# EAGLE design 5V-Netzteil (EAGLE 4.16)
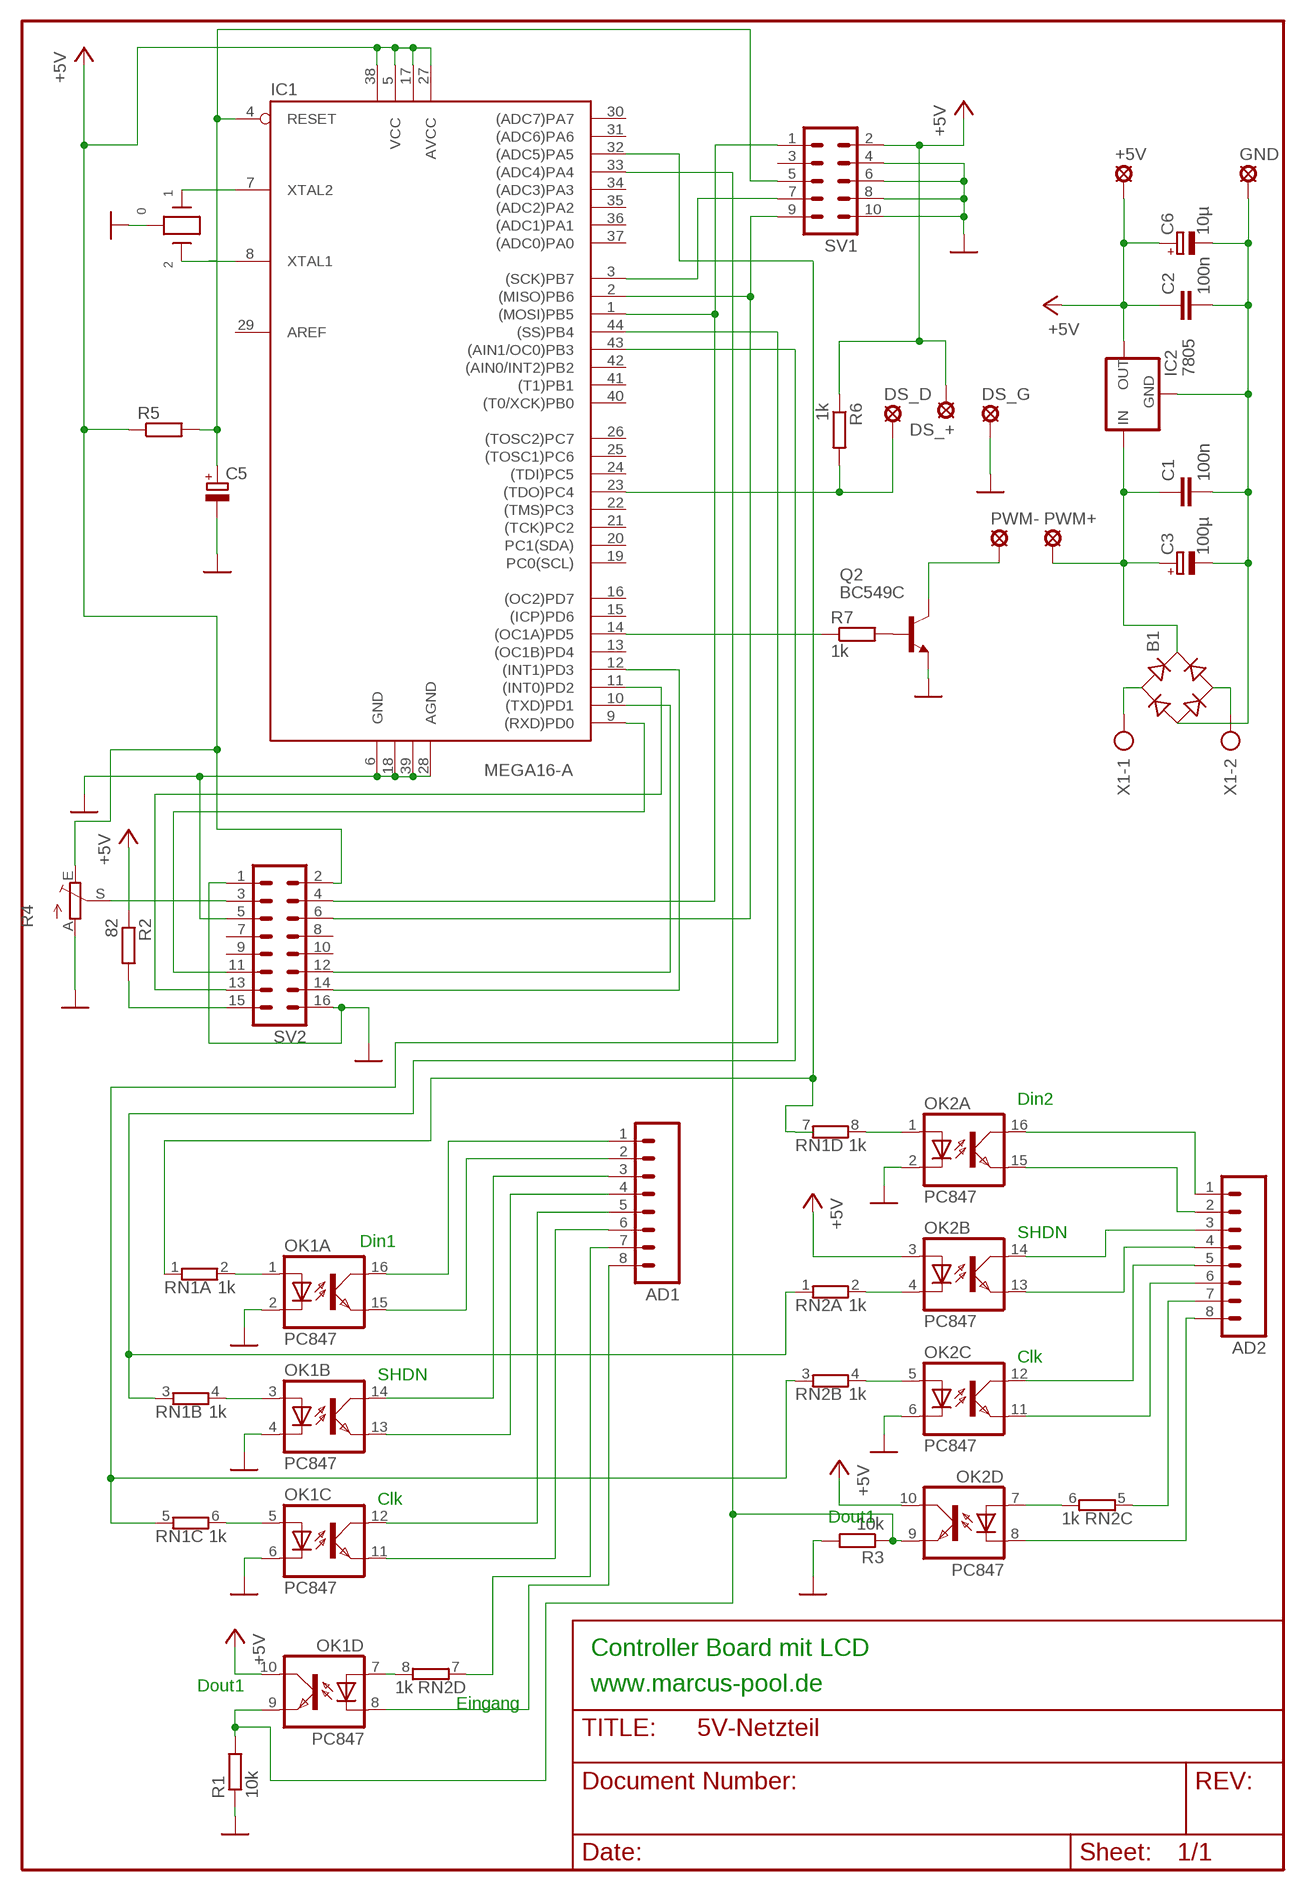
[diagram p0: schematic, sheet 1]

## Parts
+5V  DS1820  LSP10  [LSP10]
AD1  M08  [08P]
AD2  M08  [08P]
B1  B-DIL  [B-DIL]
C1  100n  C-EU050-030X075  [C050-030X075]
C2  100n  C-EU050-030X075  [C050-030X075]
C3  100µ  CPOL-EUE5-13  [E5-13]
C5  CPOL-EUE2-5  [E2-5]
C6  10µ  CPOL-EUE2,5-6E  [E2,5-6E]
DS_+  DS1820  LSP10  [LSP10]
DS_D  DS1820  LSP10  [LSP10]
DS_G  DS1820  LSP10  [LSP10]
GND  DS1820  LSP10  [LSP10]
IC1  MEGA16-A  [TQFP44]
IC2  7805  78XXS  [78XXS]
OK1  PC847  [DIL16]
OK2  PC847  [DIL16]
PWM+  DS1820  LSP10  [LSP10]
PWM-  DS1820  LSP10  [LSP10]
Q2  BC549C  [TO92-EBC]
Q/1  SCHWINGER/3"  [SCHWINGER/3]
R1  10k  R-EU_0207/10  [0207/10]
R2  82  R-EU_0207/10  [0207/10]
R3  10k  R-EU_0207/10  [0207/10]
R4  TRIM_EU-LI10  [LI10]
R5  R-EU_0207/10  [0207/10]
R6  1k  R-EU_0207/10  [0207/10]
R7  1k  R-EU_0207/10  [0207/10]
RN1  1k  E4R  [SIL8]
RN2  1k  E4R  [SIL8]
SV1  ML10  [ML10]
SV2  ML16  [ML16]
X1  AK500/2  [AK500/2]

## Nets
+5V: +5V.MP C2.1 C6.+ DS_+.MP IC1.5(VCC) IC1.17(VCC1) IC1.27(AVCC) IC1.38(VCC2) IC2.OUT OK1.10(D:COL) OK2.3(B:A) OK2.10(D:COL) R2.1 R4.E R5.1 R6.1 SV1.2 SV2.2
CLK: IC1.44((SS)PB4) RN1.5 RN2.3
DIN: IC1.32((ADC5)PA5) RN1.1 RN1.7
DIN2A: OK1.1(A:A) RN1.2
DIN2B: OK2.1(A:A) RN1.8
DOUT: IC1.33((ADC4)PA4) OK1.9(D:EMIT) OK2.9(D:EMIT) R1.2 R3.1
GND: B1.- C1.2 C2.2 C3.- C5.- C6.- DS_G.MP GND.MP IC1.6(GND) IC1.18(GND1) IC1.28(AGND) IC1.39(GND2) IC2.GND OK1.2(A:C) OK1.4(B:C) OK1.6(C:C) OK2.2(A:C) OK2.6(C:C) Q2.E Q/1.0 R1.1 R3.2 R4.A SV1.4 SV1.6 SV1.8 SV1.10 SV2.1 SV2.5 SV2.16 ; supply symbol labelled 
N$1: Q2.B R7.2
N$2: OK2.4(B:C) RN2.2
N$3: B1.AC1 X1.1
N$4: B1.AC2 X1.2
N$5: B1.+ C1.1 C3.+ IC2.IN PWM+.MP
N$6: PWM-.MP Q2.C
N$7: IC1.12((INT1)PD3) SV2.14
N$8: IC1.7(XTAL2) Q/1.1
N$9: IC1.1((MOSI)PB5) SV1.1 SV2.4
N$10: IC1.8(XTAL1) Q/1.2
N$12: IC1.10((TXD)PD1) SV2.12
N$13: IC1.11((INT0)PD2) SV2.13
N$14: IC1.9((RXD)PD0) SV2.11
N$17: R4.S SV2.3
N$18: OK1.5(C:A) RN1.6
N$19: OK1.3(B:A) RN1.4
N$20: OK1.7(D:A) RN2.8
N$21: OK2.7(D:A) RN2.6
N$22: OK2.5(C:A) RN2.4
N$24: R2.2 SV2.15
N$26: IC1.2((MISO)PB6) SV1.9 SV2.6
N$27: IC1.3((SCK)PB7) SV1.7
N$28: AD2.6 OK2.11(C:EMIT)
N$30: AD1.2 OK1.15(A:EMIT)
N$34: AD1.1 OK1.16(A:COL)
N$36: AD2.1 OK2.16(A:COL)
N$37: AD2.2 OK2.15(A:EMIT)
N$38: AD2.3 OK2.14(B:COL)
N$39: AD2.4 OK2.13(B:EMIT)
N$40: AD1.3 OK1.14(B:COL)
N$41: AD1.4 OK1.13(B:EMIT)
N$42: AD1.5 OK1.12(C:COL)
N$43: AD1.6 OK1.11(C:EMIT)
N$44: AD1.7 RN2.7
N$45: AD1.8 OK1.8(D:C)
N$46: AD2.5 OK2.12(C:COL)
N$48: AD2.7 RN2.5
N$49: AD2.8 OK2.8(D:C)
N$52: IC1.14((OC1A)PD5) R7.1
N$53: DS_D.MP IC1.23((TDO)PC4) R6.2
RESET: C5.+ IC1.4(RESET) R5.2 SV1.5
SHDN: IC1.43((AIN1/OC0)PB3) RN1.3 RN2.1
Unconnected: IC1.13((OC1B)PD4) IC1.15((ICP)PD6) IC1.16((OC2)PD7) IC1.19(PC0(SCL)) IC1.20(PC1(SDA)) IC1.21((TCK)PC2) IC1.22((TMS)PC3) IC1.24((TDI)PC5) IC1.25((TOSC1)PC6) IC1.26((TOSC2)PC7) IC1.30((ADC7)PA7) IC1.31((ADC6)PA6) IC1.34((ADC3)PA3) IC1.35((ADC2)PA2) IC1.36((ADC1)PA1) IC1.37((ADC0)PA0) IC1.40((T0/XCK)PB0) IC1.41((T1)PB1) IC1.42((AIN0/INT2)PB2) SV1.3 SV2.7 SV2.8 SV2.9 SV2.10

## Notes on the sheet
- Din2
- SHDN
- Din1
- Clk
- SHDN
- Clk
- Dout1
- Controller Board mit LCD
- Dout1 | www.marcus-pool.de
- Eingang

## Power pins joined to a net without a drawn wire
AREF: IC1.29(AREF)

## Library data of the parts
+5V DS_+ DS_D DS_G GND PWM+ PWM- = solpad:LSP10: SOLDER PAD
AD1 AD2 = con-amp-quick:M08: AMP QUICK CONNECTOR
B1 = rectifier:B-DIL: RECTIFIER
C1 C2 = rcl:C-EU: CAPACITOR, European symbol
C3 C5 C6 = rcl:CPOL-EU: POLARIZED CAPACITOR, European symbol
IC1 = atmel:MEGA16: MICROCONTROLLER 16 Kbytes FLASH 1 kbytes SRAM 512 bytes EEPROM USART 8-channel 10 bit ADC
IC2 = v-reg:78XXS: VOLTAGE REGULATOR
OK1 OK2 = optocoupler:PC847: SHARP OPTO COUPLER
Q2 = transistor-npn:BC549*: NPN Transistor
Q/1 = crystal2:SCHWINGER/3: Schwinger 4 MHz
R1-R3 R5-R7 = rcl:R-EU_: RESISTOR, European symbol
R4 = pot:TRIM_EU-: POTENTIOMETER
RN1 RN2 = resistor-sil:E4R: SIL RESISTOR
SV1 = con-harting-ml:ML10: HARTING
SV2 = con-harting-ml:ML16: HARTING
X1 = con-ptr500:AK500/2: CONNECTOR

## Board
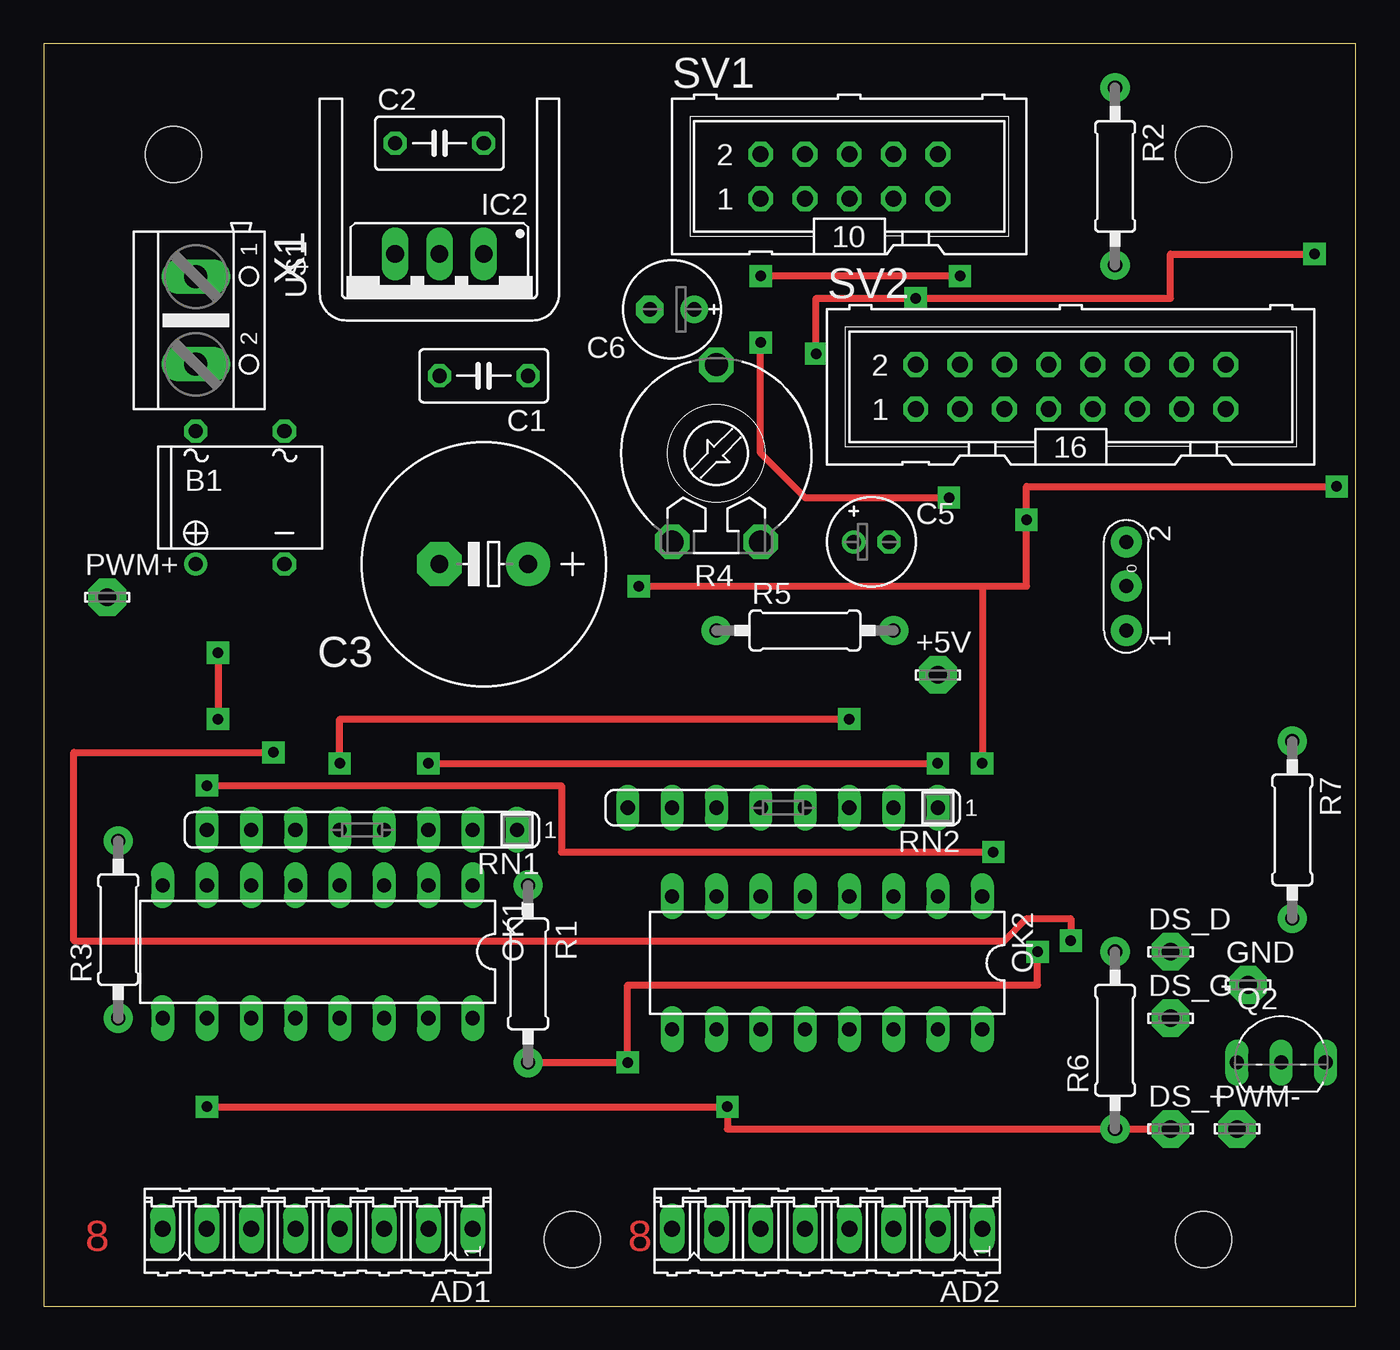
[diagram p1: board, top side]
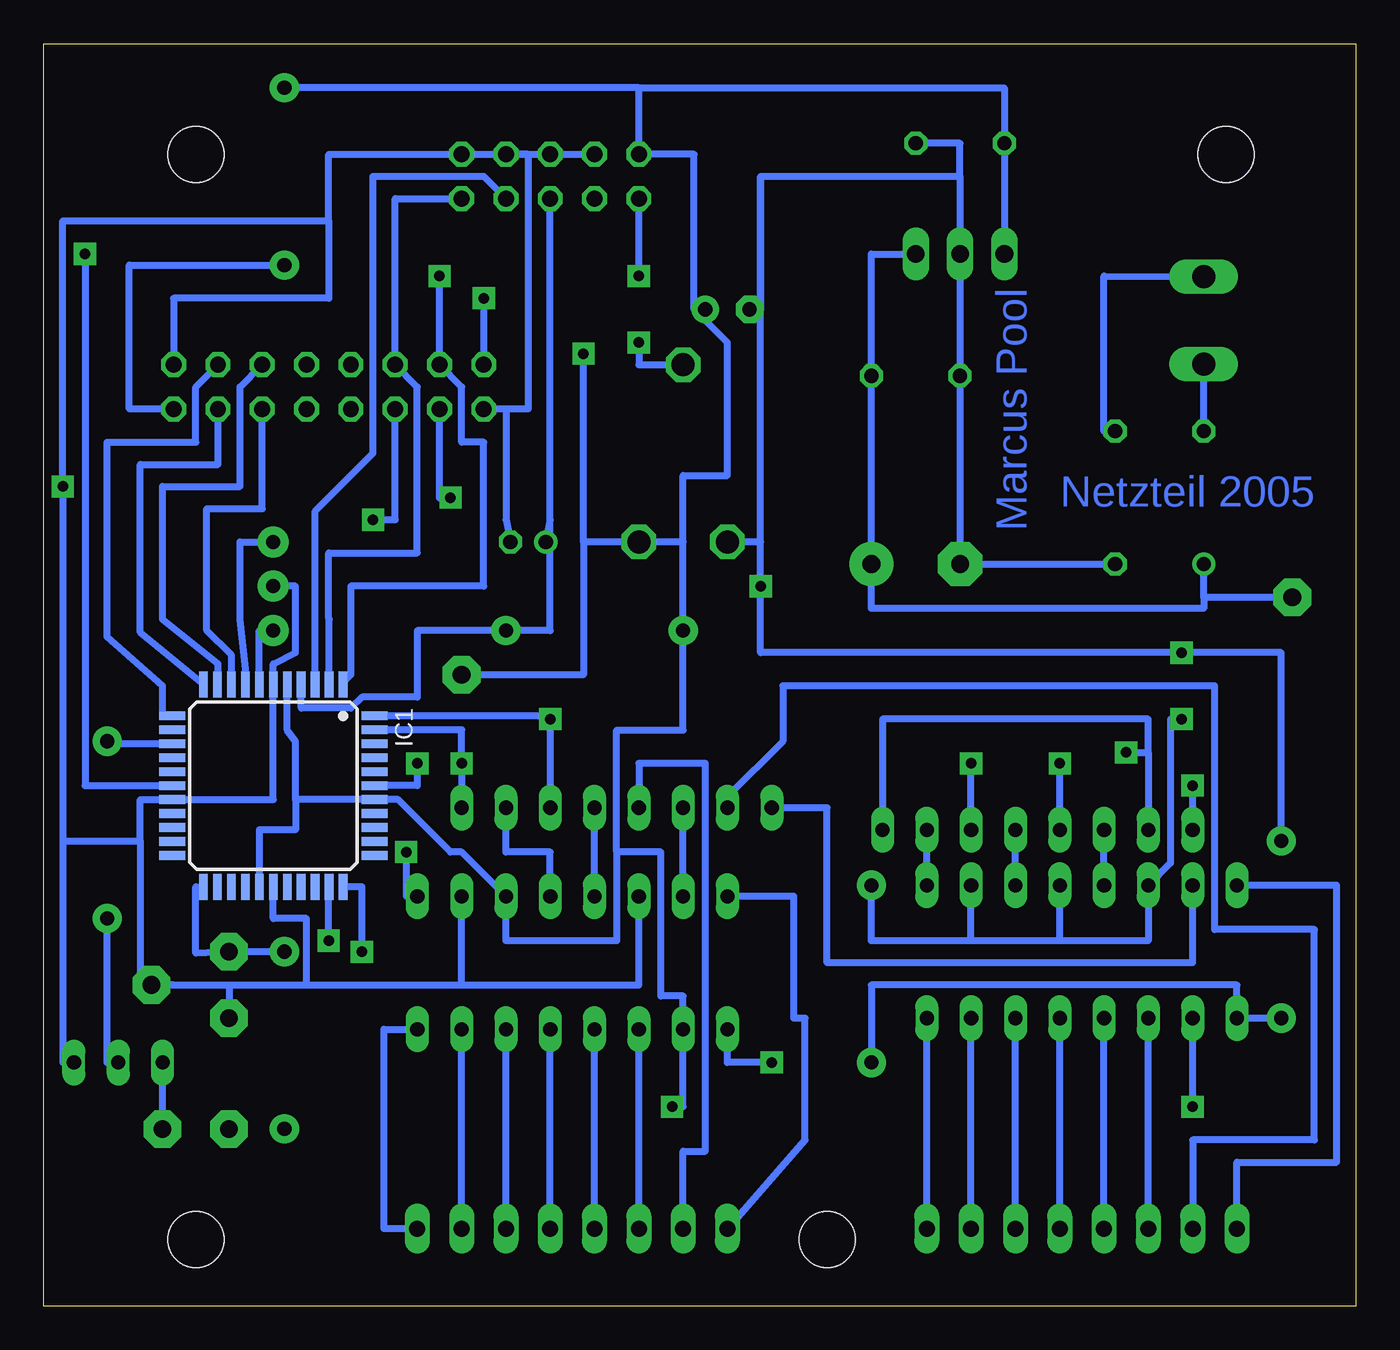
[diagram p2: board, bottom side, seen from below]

Size 75.23 x 72.38 mm. Coordinates in mm from the lower left corner, seen from the top.
Outline: 0,0 75.23,0 75.23,72.38 0,72.38 0,0
Copper layers (1*16): Top 0.035mm / dielectric 1.5mm / Bottom 0.035mm
Design rules "default": minimum track width 10mil, minimum drill 24mil, track to track 8mil, track to pad 8mil, pad to pad 8mil, via to via 8mil, smd to smd 8mil, copper to edge 40mil, drill to drill 8mil, minimum pad ring 10mil, minimum via ring 8mil, stop-mask expansion 4mil, vias tented up to drill 0mil, thermal gap 10mil
Holes 3.2 mm at 7.46,66.04 66.51,66.04 66.51,3.81 30.31,3.81

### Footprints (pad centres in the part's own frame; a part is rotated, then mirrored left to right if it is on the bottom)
LSP10 = drill 1.016 pad 2.159 octagon: MP 0,0
08P = drill 0.914 long: 1 -8.89,0; 2 -6.35,0; 3 -3.81,0; 4 -1.27,0; 5 1.27,0; 6 3.81,0; 7 6.35,0; 8 8.89,0
B-DIL = drill 0.813 round: + -2.54,-3.81 | drill 0.813 octagon: - 2.54,-3.81; AC1 2.54,3.81; AC2 -2.54,3.81
C050-030X075 = drill 0.813 octagon: 1 -2.54,0; 2 2.54,0
E5-13 = drill 1.016 pad 2.54 round: + -2.54,0 | drill 1.016 pad 2.54 octagon: - 2.54,0
E2-5 = drill 0.813 pad 1.27 round: + -1.016,0 | drill 0.813 pad 1.27 octagon: - 1.016,0
E2,5-6E = drill 0.813 pad 1.575 round: + -1.27,0 | drill 0.813 pad 1.575 octagon: - 1.27,0
TQFP44 = smd 1.5 x 0.5: 1 -5.8,4; 2 -5.8,3.2; 3 -5.8,2.4; 4 -5.8,1.6; 5 -5.8,0.8; 6 -5.8,0; 7 -5.8,-0.8; 8 -5.8,-1.6; 9 -5.8,-2.4; 10 -5.8,-3.2; 11 -5.8,-4; 23 5.8,-4; 24 5.8,-3.2; 25 5.8,-2.4; 26 5.8,-1.6; 27 5.8,-0.8; 28 5.8,0; 29 5.8,0.8; 30 5.8,1.6; 31 5.8,2.4; 32 5.8,3.2; 33 5.8,4 | smd 0.5 x 1.5: 12 -4,-5.8; 13 -3.2,-5.8; 14 -2.4,-5.8; 15 -1.6,-5.8; 16 -0.8,-5.8; 17 0,-5.8; 18 0.8,-5.8; 19 1.6,-5.8; 20 2.4,-5.8; 21 3.2,-5.8; 22 4,-5.8; 34 4,5.8; 35 3.2,5.8; 36 2.4,5.8; 37 1.6,5.8; 38 0.8,5.8; 39 0,5.8; 40 -0.8,5.8; 41 -1.6,5.8; 42 -2.4,5.8; 43 -3.2,5.8; 44 -4,5.8
78XXS = drill 1.016 long: GND 0,-2.54; IN -2.54,-2.54; OUT 2.54,-2.54
DIL16 = drill 0.813 long: 1 -8.89,-3.81; 2 -6.35,-3.81; 3 -3.81,-3.81; 4 -1.27,-3.81; 5 1.27,-3.81; 6 3.81,-3.81; 7 6.35,-3.81; 8 8.89,-3.81; 9 8.89,3.81; 10 6.35,3.81; 11 3.81,3.81; 12 1.27,3.81; 13 -1.27,3.81; 14 -3.81,3.81; 15 -6.35,3.81; 16 -8.89,3.81
TO92-EBC = drill 0.813 long: B 0,-1.27; C -2.54,-1.27; E 2.54,-1.27
SCHWINGER/3 = drill 0.8 pad 1.778 round: 0 0,0; 1 -2.54,0; 2 2.54,0
0207/10 = drill 0.813 pad 1.676 round: 1 -5.08,0; 2 5.08,0
LI10 = drill 1.321 octagon: A -2.54,-5.08; E 2.54,-5.08; S 0,5.08
SIL8 = drill 0.813 long: 1 -8.89,0; 2 -6.35,0; 3 -3.81,0; 4 -1.27,0; 5 1.27,0; 6 3.81,0; 7 6.35,0; 8 8.89,0
ML10 = drill 0.914 octagon: 1 -5.08,-1.27; 2 -5.08,1.27; 3 -2.54,-1.27; 4 -2.54,1.27; 5 0,-1.27; 6 0,1.27; 7 2.54,-1.27; 8 2.54,1.27; 9 5.08,-1.27; 10 5.08,1.27
ML16 = drill 0.914 octagon: 1 -8.89,-1.27; 2 -8.89,1.27; 3 -6.35,-1.27; 4 -6.35,1.27; 5 -3.81,-1.27; 6 -3.81,1.27; 7 -1.27,-1.27; 8 -1.27,1.27; 9 1.27,-1.27; 10 1.27,1.27; 11 3.81,-1.27; 12 3.81,1.27; 13 6.35,-1.27; 14 6.35,1.27; 15 8.89,-1.27; 16 8.89,1.27
AK500/2 = drill 1.321 long: 1 -2.515,0; 2 2.515,0

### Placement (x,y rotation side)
+5V  51.27,36.19 0 top
AD1  15.71,4.44 180 top
AD2  44.92,4.44 180 top
B1  11.27,46.35 0 top
C1  25.23,53.34 180 top
C2  22.7,66.67 0 top
C3  25.23,42.54 180 top
C5  47.46,43.81 0 top
C6  36.03,57.14 180 top
DS_+  64.61,10.15 0 top
DS_D  64.61,20.32 0 top
DS_G  64.61,16.51 0 top
GND  69.05,18.41 0 top
IC1  62.06,29.84 270 bottom
IC2  22.7,57.78 180 top
OK1  15.71,20.32 180 top
OK2  44.92,19.68 180 top
PWM+  3.64,40.63 0 top
PWM-  68.41,10.15 0 top
Q2  70.95,15.23 0 top
Q/1  62.06,41.27 90 top
R1  27.77,19.05 270 top
R2  61.43,64.77 270 top
R3  4.28,21.59 90 top
R4  38.57,48.89 0 top
R5  43.65,38.73 0 top
R6  61.43,15.23 90 top
R7  71.59,27.3 270 top
RN1  18.25,27.3 180 top
RN2  42.38,28.57 180 top
SV1  46.19,64.77 0 top
SV2  58.89,52.7 0 top
U$1  [D01S]  22.7,57.78 0 top
X1  8.73,56.51 270 top

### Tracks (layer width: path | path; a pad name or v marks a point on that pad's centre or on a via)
+5V  (via drill 0.6 pad 1.27)
  Top 0.406: v9.36,11.42 v39.2,11.42 39.2,10.15 R6.1 DS_+.MP | v44.28,54.6 44.28,57.78 v50,57.78 64.61,57.78 64.61,60.32 v72.86,60.32
  Bottom 0.406: IC2.OUT C2.1 20.15,69.84 41.11,69.84 | 41.11,69.84 R2.1 | 42.38,26.03 39.84,26.03 39.84,17.78 38.57,17.78 OK2.10 38.57,11.42 v39.2,11.42 | 42.38,26.03 42.38,33.02 38.57,33.02 R5.1 38.57,43.81 | 38.57,43.81 38.57,47.62 36.03,47.62 36.03,55.24 37.3,56.51 C6.+ 37.94,57.14 37.94,66.04 SV1.2 41.11,69.84 | v9.36,11.42 OK1.10 | 42.38,26.03 42.38,20.95 48.73,20.95 OK2.3 51.27,26.03 51.91,26.03 54.91,29.04 IC1.38 60.8,29.04 60.8,29.21 | 44.28,43.81 44.28,36.19 +5V.MP | 44.28,43.81 v44.28,54.6 | v50,57.78 SV2.2 | 60.8,29.21 60.8,32.38 61.27,33.02 IC1.5 | 38.57,43.81 R4.E 44.28,43.81 | IC1.27 62.87,27.3 60.8,27.3 60.8,29.21 | IC1.17 72.86,29.84 v72.86,60.32
CLK  (via drill 0.6 pad 1.27)
  Top 0.406: v16.98,31.11 16.98,33.65 v46.19,33.65
  Bottom 0.406: RN2.3 v46.19,33.65 46.19,33.84 IC1.44 | RN1.5 v16.98,31.11
DIN  (via drill 0.6 pad 1.27)
  Top 0.406: v58.89,20.95 58.89,22.22 56.35,22.22 55.08,20.95 1.74,20.95 1.74,31.75 v13.17,31.75
  Bottom 0.406: 11.9,31.75 RN1.7 | 11.9,31.75 11.9,33.65 27.14,33.65 RN1.1 | IC1.32 58.89,24.04 v58.89,20.95 | v13.17,31.75 11.9,31.75
DIN2A
  Bottom 0.406: OK1.1 RN1.2
DIN2B  (via drill 0.6 pad 1.27)
  Top 0.406: v54.45,26.03 29.68,26.03 29.68,29.84 v9.36,29.84
  Bottom 0.406: v54.45,26.03 54.45,23.49 OK2.1 | RN1.8 v9.36,29.84
DOUT  (via drill 0.6 pad 1.27)
  Top 0.406: R1.2 v33.49,13.96 33.49,18.41 56.98,18.41 v56.98,20.32
  Bottom 0.406: R3.1 OK1.9 6.82,18.41 27.77,18.41 R1.2 | v33.49,13.96 36.03,13.96 OK2.9 | IC1.33 56.98,24.04 v56.98,20.32
GND  (via drill 0.6 pad 1.27)
  Top 0.406: v10,37.46 v10,33.65 | v74.13,46.98 56.35,46.98 v56.35,45.08 56.35,41.27 53.81,41.27 | v34.12,41.27 53.81,41.27 | 53.81,41.27 v53.81,31.11
  Bottom 0.406: SV1.4 SV1.6 47.46,66.04 | 47.46,66.04 SV1.10 58.89,66.04 58.89,62.22 | 47.46,66.04 SV1.8 | 16.98,20.95 OK1.4 | 16.98,20.95 22.06,20.95 | 22.06,20.95 OK1.2 | 16.98,20.95 11.9,20.95 OK1.6 10.63,25.39 10.63,33.65 v10,33.65 | OK2.6 41.11,18.41 51.27,18.41 | 51.27,18.41 OK2.2 | 67.78,18.41 64.61,18.41 | 64.61,18.41 60.16,18.41 | 60.16,18.41 51.27,18.41 | 58.89,62.22 74.13,62.22 v74.13,46.98 74.13,26.67 | 58.89,62.22 58.89,57.78 67.78,57.78 SV2.16 | B1.- C3.- C1.2 IC2.GND 22.7,64.77 | C2.2 22.7,66.67 22.7,64.77 | 34.12,57.14 C6.- | 34.12,64.77 22.7,64.77 | 34.12,43.81 34.12,57.14 | 34.12,64.77 34.12,57.14 | 67.78,18.41 GND.MP | 67.78,18.41 69.69,18.41 69.69,26.67 | v34.12,41.27 34.12,37.46 v10,37.46 4.28,37.46 R3.2 | v34.12,41.27 34.12,43.81 | R1.1 27.77,20.95 22.06,20.95 | 34.12,43.81 R4.A | 47.46,66.04 47.46,51.43 48.73,51.43 | Q/1.0 60.8,41.27 60.8,37.46 62.06,36.82 IC1.6 62.06,29.04 IC1.18 69.69,29.04 69.69,26.67 | 48.73,51.43 SV2.1 | SV2.5 55.08,45.08 v56.35,45.08 | v34.12,41.27 34.12,64.77 | 74.13,26.67 74.13,13.96 Q2.E | 64.61,18.41 DS_G.MP | 74.13,26.67 69.69,26.67 | C5.- 48.73,45.08 48.73,51.43 | IC1.28 62.06,22.22 60.16,22.22 60.16,18.41 | IC1.39 53.81,29.84 v53.81,31.11
N$1
  Bottom 0.406: Q2.B 71.59,13.96 R7.2
N$2
  Bottom 0.406: OK2.4 46.19,26.03 48.73,26.03 RN2.2
N$3
  Bottom 0.406: B1.AC1 14.44,50.16 14.44,59.05 X1.1
N$4
  Bottom 0.406: B1.AC2 X1.2
N$5
  Bottom 0.406: 8.73,40.63 8.73,40 27.77,40 C3.+ C1.1 27.77,60.32 IC2.IN | 8.73,40.63 B1.+ | PWM+.MP 8.73,40.63
N$6
  Bottom 0.406: PWM-.MP Q2.C
N$7
  Bottom 0.406: SV2.14 66.51,52.7 66.51,49.52 71.59,49.52 71.59,38.37 68.41,35.55 68.41,33.84 IC1.12
N$8
  Bottom 0.406: IC1.7 62.87,38.73 Q/1.1
N$9  (via drill 0.6 pad 1.27)
  Top 0.406: v52.54,59.05 v41.11,59.05
  Bottom 0.406: v41.11,59.05 SV1.1 | v52.54,59.05 SV2.4 51.27,52.7 51.27,49.52 50,49.52 50,41.27 57.62,41.27 57.62,36.19 58.06,35.74 IC1.1
N$10
  Bottom 0.406: IC1.8 63.66,36.52 63.97,39.36 63.97,43.81 Q/1.2
N$12
  Bottom 0.406: SV2.12 63.97,52.7 63.97,46.98 68.41,46.98 68.41,39.36 65.24,36.82 65.24,35.64 IC1.10
N$13
  Bottom 0.406: IC1.11 69.69,38.62 69.69,48.25 65.24,48.25 SV2.13
N$14
  Bottom 0.406: SV2.11 62.7,45.71 65.88,45.71 65.88,38.73 64.47,37.32 IC1.9
N$17  (via drill 0.6 pad 1.27)
  Top 0.406: v41.11,55.24 41.11,48.89 43.65,46.35 v51.91,46.35
  Bottom 0.406: v51.91,46.35 52.54,46.35 SV2.3 | R4.S 41.11,53.97 v41.11,55.24
N$18
  Bottom 0.406: OK1.5 RN1.6
N$19
  Bottom 0.406: OK1.3 RN1.4
N$20
  Bottom 0.406: OK1.7 9.36,19.68 30.31,19.68 30.31,28.57 RN2.8
N$21
  Bottom 0.406: OK2.7 RN2.6
N$22
  Bottom 0.406: OK2.5 RN2.4
N$24
  Bottom 0.406: SV2.15 70.32,51.43 70.32,59.68 R2.2
N$26
  Bottom 0.406: SV1.9 55.08,63.49 SV2.6 53.81,52.7 53.81,43.17 58.89,43.17 58.89,39.41 58.87,39.39 IC1.2
N$27
  Bottom 0.406: IC1.3 59.66,45.57 56.35,48.89 56.35,64.77 50,64.77 SV1.7
N$28
  Bottom 0.406: AD2.6 OK2.11
N$30
  Bottom 0.406: AD1.2 OK1.15
N$34
  Bottom 0.406: AD1.1 OK1.16
N$36
  Bottom 0.406: OK2.16 55.71,15.87 55.71,4.44 AD2.1
N$37
  Bottom 0.406: AD2.2 OK2.15
N$38
  Bottom 0.406: AD2.3 OK2.14
N$39
  Bottom 0.406: AD2.4 OK2.13
N$40
  Bottom 0.406: AD1.3 OK1.14
N$41
  Bottom 0.406: AD1.4 OK1.13
N$42
  Bottom 0.406: AD1.5 OK1.12
N$43
  Bottom 0.406: AD1.6 OK1.11
N$44
  Bottom 0.406: RN2.7 36.03,29.21 32.85,32.38 32.85,35.55 8.09,35.55 8.09,21.59 2.38,21.59 2.38,9.52 9.36,9.52 AD1.7
N$45
  Bottom 0.406: AD1.8 6.82,8.25 1.1,8.25 1.1,24.12 OK1.8
N$46
  Bottom 0.406: AD2.5 OK2.12
N$48
  Bottom 0.406: AD2.7 38.57,8.88 37.3,8.88 37.3,31.11 41.11,31.11 RN2.5
N$49
  Bottom 0.406: AD2.8 31.58,9.52 31.58,16.51 32.22,16.51 32.22,23.49 OK2.8
N$52
  Bottom 0.406: IC1.14 71.59,32.24 R7.1
N$53
  Bottom 0.406: R6.2 DS_D.MP 66.51,20.23 66.51,24.04 IC1.23
RESET
  Bottom 0.406: 46.19,38.73 R5.2 53.81,38.73 53.81,34.92 56.98,34.92 57.62,34.28 60.46,34.28 IC1.4 | C5.+ 46.19,45.08 46.19,38.73 | 46.19,38.73 SV1.5
SHDN  (via drill 0.6 pad 1.27)
  Top 0.406: v22.06,31.11 v51.27,31.11
  Bottom 0.406: RN2.1 v51.27,31.11 51.27,33.04 IC1.43 | RN1.3 v22.06,31.11

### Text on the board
Top: 8 | 8
Bottom: Netzteil 2005 | Marcus Pool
